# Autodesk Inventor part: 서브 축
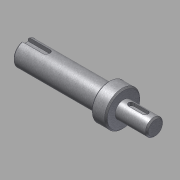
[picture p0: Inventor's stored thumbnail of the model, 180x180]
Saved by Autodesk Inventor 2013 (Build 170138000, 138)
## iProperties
Created: 2014-10
Part Number: 서브 축
Document SubType Name: Modeling
Designer: KYOUNG IL JANG
Density: 1 g/cm^3
Mass: 19.9624 g
Surface Area: 57.7178 cm^2
Volume: 19.9624 cm^3
Material: 강철, 연강
Author: SeoGD™ [www.esajin.kr]
Revision Number: 1
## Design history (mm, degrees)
sketch "스케치1"
  geometry: L1 (-16.331, 0)-(-108.831, 0); L2 (-16.331, 0)-(-16.331, -6); L3 (-16.331, -6)-(-38.831, -6); L4 (-38.831, -12.5)-(-46.5, -12.5); L5 (-46.5, -8.5)-(-108.831, -8.5); L6 (-108.831, -8.5)-(-108.831, 0); L7 (-46.5, -8.5)-(-46.5, -12.5); L8 (-38.831, -6)-(-38.831, -12.5); L9 (-46.5, 12.249)-(-46.5, -12.249) reference; L10 (-38.831, -17)-(-38.831, 17) reference; 2 further points
  constraints: 17 end point, 4 perpendicular, 2 collinear, 2 parallel, 1 horizontal, 1 midpoint, 1 point on line
  dimensions: "d1" = 12 diameter of L3 L1; "d2" = 25 diameter of L4 L1; "d3" = 17 diameter of L5 L1; "d18" = 22.5 distance of L2.end L3.end; "d20" = 70 distance between parallel lines of L6 L8; "d21" = 7.66872 distance of L4.start L4.end (derived)
revolve "회전1" sketch "스케치1" stored, may be unused: angle "d5" = 90 deg
chamfer "모따기1" distance "d6" = 1; stored, may be unused: second distance "d7" = 2, angle "d8" = 45 deg
node "작업 평면1"
sketch "스케치2"
  geometry: L1 (11.25, 5)-(11.25, -5) reference; L2 (-5.75, -2)-(4.25, -2); L3 (4.25, 2)-(-5.75, 2); A1 r 2 centre (4.25, 0) between (4.25, -2) and (4.25, 2); A2 r 2 centre (-5.75, 0) between (-5.75, 2) and (-5.75, -2); 2 further points
  constraints: 4 end point, 4 point on circle, 4 tangent, 2 centre point, 1 horizontal alignment, 1 midpoint, 1 parallel, 1 perpendicular
  dimensions: "d9" = 4 distance between parallel lines of L2 L3; "d10" = 14 dimension on A1 A2; "d11" = 5 distance edge to line of A1 L1
extrude "돌출1" cut sketch "스케치2" distance "d12" = 2.5; taper "d13" = 0 deg
node "작업 평면2"
sketch "스케치3"
  geometry: L1 (-31.166, -7.5)-(-31.166, 7.5) reference; L2 (-31.166, 2.5)-(-15.666, 2.5); L3 (-15.666, -2.5)-(-31.166, -2.5); A1 r 2.5 centre (-15.666, 0) between (-15.666, -2.5) and (-15.666, 2.5); 2 further points
  constraints: 4 end point, 2 perpendicular, 2 point on circle, 2 point on line, 2 tangent, 1 centre point, 1 horizontal alignment, 1 midpoint
  dimensions: "d14" = 5 distance between parallel lines of L3 L2; "d15" = 18 dimension on A1 L1
extrude "돌출2" cut sketch "스케치3" distance "d16" = 3; taper "d17" = 0 deg
sketch "스케치4"
  geometry: C1 r 12.5 at (0, 0) reference; 1 further point
extrude "돌출3" join sketch "스케치4" distance "d22" = 3; taper "d23" = 0 deg
chamfer "모따기2" distance "d24" = 1; stored, may be unused: second distance "d25" = 2, angle "d26" = 45 deg
node "솔리드1"
node "참조4"
node "참조5"
